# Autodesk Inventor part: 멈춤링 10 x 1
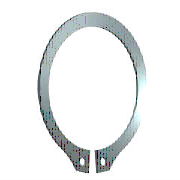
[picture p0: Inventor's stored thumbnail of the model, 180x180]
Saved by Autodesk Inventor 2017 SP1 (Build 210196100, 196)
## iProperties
IsCustomPart: 0
Created: 2021-07
Part Number: 멈춤링 10 x 1
Material: 강철, 연강
Description: 리테이닝 링(C형)
Document SubType Name: Modeling
Standard: KS B 1336
Designer: mdu
Standards Organization: KS
Language: ko-KR
Size Designation: 10 x 1
Categories: <MemberInstance><Categories><Category DisplayName="샤프트 부품" InternalName="7f7aeb1f-a693-4053-b835-cee3144e0d98" Mnemonic="SHFT"><Category DisplayName="써클립" Inter
Density: 7.86 g/cm^3
Mass: 0.423087 g
Surface Area: 1.9243 cm^2
Volume: 0.0538279 cm^3
Appearance: 파란색 - 벽 페인트 - 광택
Author: mdu
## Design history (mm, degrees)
sketch "스케치1"
  geometry: L1 (-6, 0)-(6, 0) reference; L2 (0, 20.189)-(0, -80.536) reference; L3 (-48.09, 0)-(48.09, 0) reference; L4 (-0.3, -9.791)-(-0.3, -12.791); L5 (-0.3, -6.54)-(-0.3, -13.29); L6 (-2.795, 1.6)-(3.672, 1.6); L7 (0.3, -6.54)-(0.3, -13.29); L8 (0.3, -9.791)-(0.3, -12.791); C1 r 0.6 at (-1.2, -11.486); C2 r 0.6 at (1.2, -11.486); A1 r 4.8 centre (0, -5) between (0.3, -9.791) and (-0.3, -9.791); A2 r 6.2 centre (0, -4.6) between (2.988, -10.033) and (-2.988, -10.033); A3 r 7.796 centre (0, -5) between (-1.418, -12.666) and (-0.3, -12.791); A4 r 1.2 centre (-1.2, -11.486) between (-2.383, -11.285) and (-1.418, -12.666); A5 r 1.2 centre (-3.566, -11.084) between (-2.383, -11.285) and (-2.988, -10.033); A6 r 1.2 centre (3.566, -11.084) between (2.988, -10.033) and (2.383, -11.285); A7 r 1.2 centre (1.2, -11.486) between (1.418, -12.666) and (2.383, -11.285); A8 r 7.796 centre (0, -5) between (0.3, -12.791) and (1.418, -12.666)
  constraints: 16 point on circle, 12 end point, 10 centre point, 9 symmetric about line, 5 point on line, 4 tangent, 3 coincident, 2 horizontal, 1 perpendicular, 1 vertical, 5 other
  dimensions: "d0" = 9.6 diameter of A1 (= ND); "d1" = 3 distance of L4.end L4.start (= SRB2); "d6" = 0.3 distance between parallel lines of L2 L5 (= 0.25 x SD5); "d7" = 1.6 distance between parallel lines of L6 L3 (= SRB1); "d8" = 0.4 distance of A1.centre A2.centre (= 0.25 x SRB1); "d9" = 1.2 radius of A4 (= SD5); "d10" = 1.2 radius of A5 (= SD5); "d11" = 0.9 distance from line of L4 A4.centre (= 0.75 x SD5); "d12" = 1.2 diameter of C1 (= SD5); "d13" = 1.2 diameter of C2 (= SD5); "d14" = 5 distance from line of A1.centre L1 (= 0.5 x WD)
extrude "본체" new body sketch "스케치1" distance "d2" = 1 (= SD); taper "d3" = 0 deg
workaxis "Work Axis1"
workplane "Work Plane1"
body "Solid1"
other parameters: "SD" = 1 [user parameter; used in 1 equation term], "SRB1" = 1.6 [user parameter; used in 2 equation terms], "ND" = 9.6 [user parameter; used in 1 equation term], "SRB2" = 3 [user parameter; used in 1 equation term], "SD5" = 1.2 [user parameter; used in 6 equation terms], "d15" = 0, "d16" = 0, "d17" = 0, "d41" = 0, "d42" = 0, "SD3" = 9.3 [user parameter], "WDMAX" = 11 [user parameter]
